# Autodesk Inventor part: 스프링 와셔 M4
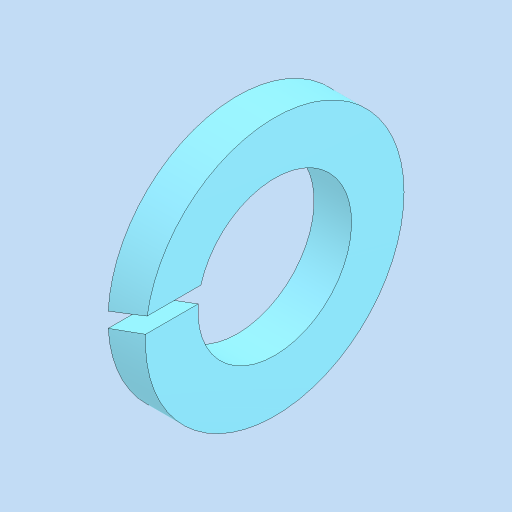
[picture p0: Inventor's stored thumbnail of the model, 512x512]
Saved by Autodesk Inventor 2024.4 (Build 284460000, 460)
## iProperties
Created: 2026-07
Part Number: 스프링 와셔 M4
Material: 강철, 연강
Description: 스프링 잠금 와셔
Document SubType Name: Modeling
Designer: home
Density: 7.85 g/cm^3
Appearance: 기본값
Author: jhkim
Sending System: Autodesk Inventor 2027
Preprocessor: ST-DEVELOPER v20.1
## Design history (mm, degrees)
feature "Solid1"
node "솔리드1"
